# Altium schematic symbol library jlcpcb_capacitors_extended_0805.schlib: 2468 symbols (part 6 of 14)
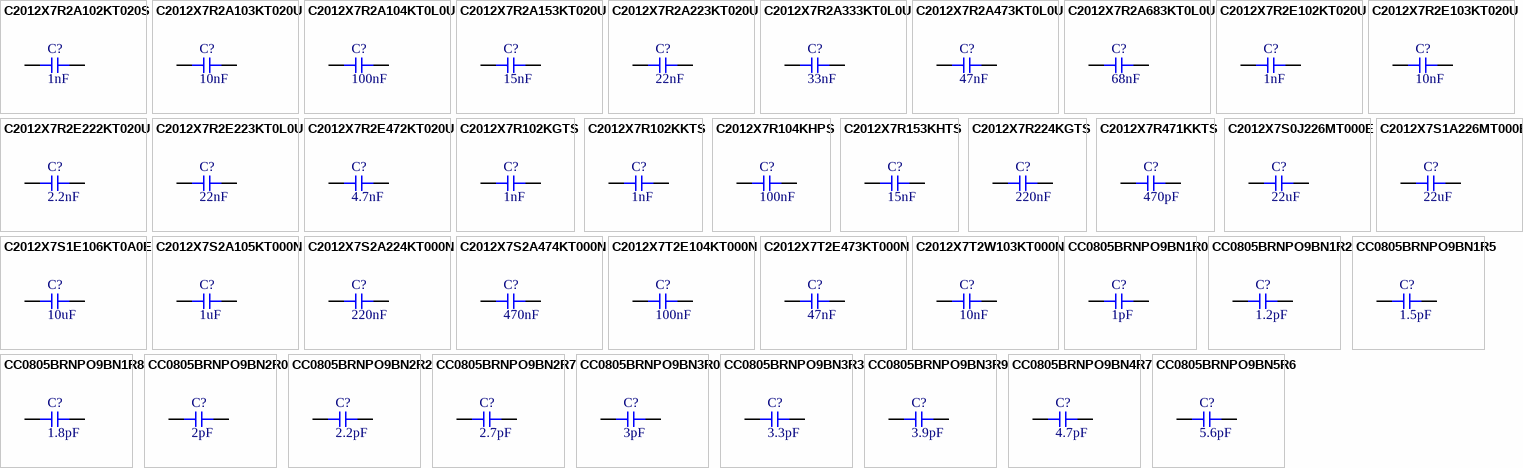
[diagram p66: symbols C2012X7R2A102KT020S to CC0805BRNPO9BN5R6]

## C2012X7T2E473KT000N
designator C?  Capacitance: 47nF  (hidden comment: *)
Capacitor, Ceramic (MLCC), 47nF, ±10%, 250V, X7T, ±10%, SMD 0805; Manufacturer: TDK; Manufacturer Part Number: C2012X7T2E473KT000N
footprint CAP-0805 (0805 (2012M) Capacitor)
pins: 1, 2

## C2012X7T2W103KT000N
designator C?  Capacitance: 10nF  (hidden comment: *)
Capacitor, Ceramic (MLCC), 10nF, ±10%, 450V, X7T, ±10%, SMD 0805; Manufacturer: TDK; Manufacturer Part Number: C2012X7T2W103KT000N
footprint CAP-0805 (0805 (2012M) Capacitor)
pins: 1, 2

## CC0805BRNPO9BN1R0
designator C?  Capacitance: 1pF  (hidden comment: *)
Capacitor, Ceramic (MLCC), 1pF, ±0.1pF, 50V, NP0, ±0.1pF, SMD 0805; Manufacturer: YAGEO; Manufacturer Part Number: CC0805BRNPO9BN1R0
footprint CAP-0805 (0805 (2012M) Capacitor)
pins: 1, 2

## CC0805BRNPO9BN1R2
designator C?  Capacitance: 1.2pF  (hidden comment: *)
Capacitor, Ceramic (MLCC), 1.2pF, ±0.1pF, 50V, NP0, ±0.1pF, SMD 0805; Manufacturer: YAGEO; Manufacturer Part Number: CC0805BRNPO9BN1R2
footprint CAP-0805 (0805 (2012M) Capacitor)
pins: 1, 2

## CC0805BRNPO9BN1R5
designator C?  Capacitance: 1.5pF  (hidden comment: *)
Capacitor, Ceramic (MLCC), 1.5pF, ±0.1pF, 50V, NP0, ±0.1pF, SMD 0805; Manufacturer: YAGEO; Manufacturer Part Number: CC0805BRNPO9BN1R5
footprint CAP-0805 (0805 (2012M) Capacitor)
pins: 1, 2

## CC0805BRNPO9BN1R8
designator C?  Capacitance: 1.8pF  (hidden comment: *)
Capacitor, Ceramic (MLCC), 1.8pF, ±0.1pF, 50V, NP0, ±0.1pF, SMD 0805; Manufacturer: YAGEO; Manufacturer Part Number: CC0805BRNPO9BN1R8
footprint CAP-0805 (0805 (2012M) Capacitor)
pins: 1, 2

## CC0805BRNPO9BN2R0
designator C?  Capacitance: 2pF  (hidden comment: *)
Capacitor, Ceramic (MLCC), 2pF, ±0.1pF, 50V, NP0, ±0.1pF, SMD 0805; Manufacturer: YAGEO; Manufacturer Part Number: CC0805BRNPO9BN2R0
footprint CAP-0805 (0805 (2012M) Capacitor)
pins: 1, 2

## CC0805BRNPO9BN2R2
designator C?  Capacitance: 2.2pF  (hidden comment: *)
Capacitor, Ceramic (MLCC), 2.2pF, ±0.1pF, 50V, NP0, ±0.1pF, SMD 0805; Manufacturer: YAGEO; Manufacturer Part Number: CC0805BRNPO9BN2R2
footprint CAP-0805 (0805 (2012M) Capacitor)
pins: 1, 2

## CC0805BRNPO9BN2R7
designator C?  Capacitance: 2.7pF  (hidden comment: *)
Capacitor, Ceramic (MLCC), 2.7pF, ±0.1pF, 50V, NP0, ±0.1pF, SMD 0805; Manufacturer: YAGEO; Manufacturer Part Number: CC0805BRNPO9BN2R7
footprint CAP-0805 (0805 (2012M) Capacitor)
pins: 1, 2

## CC0805BRNPO9BN3R0
designator C?  Capacitance: 3pF  (hidden comment: *)
Capacitor, Ceramic (MLCC), 3pF, ±0.1pF, 50V, NP0, ±0.1pF, SMD 0805; Manufacturer: YAGEO; Manufacturer Part Number: CC0805BRNPO9BN3R0
footprint CAP-0805 (0805 (2012M) Capacitor)
pins: 1, 2

## CC0805BRNPO9BN3R3
designator C?  Capacitance: 3.3pF  (hidden comment: *)
Capacitor, Ceramic (MLCC), 3.3pF, ±0.1pF, 50V, NP0, ±0.1pF, SMD 0805; Manufacturer: YAGEO; Manufacturer Part Number: CC0805BRNPO9BN3R3
footprint CAP-0805 (0805 (2012M) Capacitor)
pins: 1, 2

## CC0805BRNPO9BN3R9
designator C?  Capacitance: 3.9pF  (hidden comment: *)
Capacitor, Ceramic (MLCC), 3.9pF, ±0.1pF, 50V, NP0, ±0.1pF, SMD 0805; Manufacturer: YAGEO; Manufacturer Part Number: CC0805BRNPO9BN3R9
footprint CAP-0805 (0805 (2012M) Capacitor)
pins: 1, 2

## CC0805BRNPO9BN4R7
designator C?  Capacitance: 4.7pF  (hidden comment: *)
Capacitor, Ceramic (MLCC), 4.7pF, ±0.1pF, 50V, NP0, ±0.1pF, SMD 0805; Manufacturer: YAGEO; Manufacturer Part Number: CC0805BRNPO9BN4R7
footprint CAP-0805 (0805 (2012M) Capacitor)
pins: 1, 2

## CC0805BRNPO9BN5R6
designator C?  Capacitance: 5.6pF  (hidden comment: *)
Capacitor, Ceramic (MLCC), 5.6pF, ±0.1pF, 50V, NP0, ±0.1pF, SMD 0805; Manufacturer: YAGEO; Manufacturer Part Number: CC0805BRNPO9BN5R6
footprint CAP-0805 (0805 (2012M) Capacitor)
pins: 1, 2

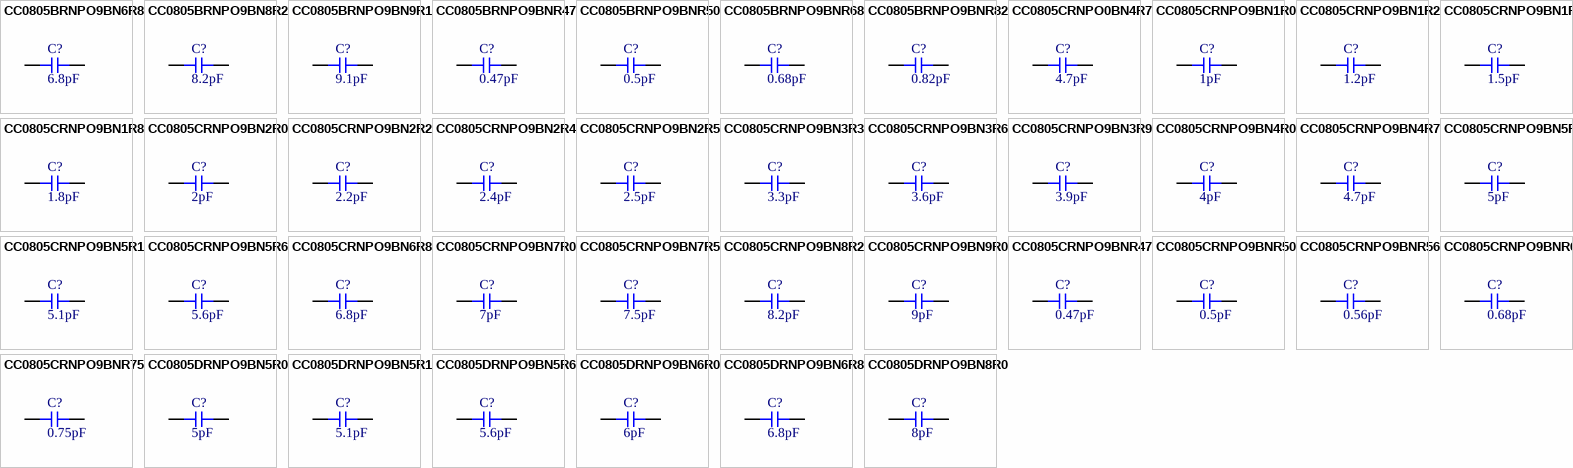
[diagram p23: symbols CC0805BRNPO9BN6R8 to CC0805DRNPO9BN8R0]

## CC0805BRNPO9BN6R8
designator C?  Capacitance: 6.8pF  (hidden comment: *)
Capacitor, Ceramic (MLCC), 6.8pF, ±0.1pF, 50V, NP0, ±0.1pF, SMD 0805; Manufacturer: YAGEO; Manufacturer Part Number: CC0805BRNPO9BN6R8
footprint CAP-0805 (0805 (2012M) Capacitor)
pins: 1, 2

## CC0805BRNPO9BN8R2
designator C?  Capacitance: 8.2pF  (hidden comment: *)
Capacitor, Ceramic (MLCC), 8.2pF, ±0.1pF, 50V, NP0, ±0.1pF, SMD 0805; Manufacturer: YAGEO; Manufacturer Part Number: CC0805BRNPO9BN8R2
footprint CAP-0805 (0805 (2012M) Capacitor)
pins: 1, 2

## CC0805BRNPO9BN9R1
designator C?  Capacitance: 9.1pF  (hidden comment: *)
Capacitor, Ceramic (MLCC), 9.1pF, ±0.1pF, 50V, NP0, ±0.1pF, SMD 0805; Manufacturer: YAGEO; Manufacturer Part Number: CC0805BRNPO9BN9R1
footprint CAP-0805 (0805 (2012M) Capacitor)
pins: 1, 2

## CC0805BRNPO9BNR47
designator C?  Capacitance: 0.47pF  (hidden comment: *)
Capacitor, Ceramic (MLCC), 0.47pF, ±0.1pF, 50V, NP0, ±0.1pF, SMD 0805; Manufacturer: YAGEO; Manufacturer Part Number: CC0805BRNPO9BNR47
footprint CAP-0805 (0805 (2012M) Capacitor)
pins: 1, 2

## CC0805BRNPO9BNR50
designator C?  Capacitance: 0.5pF  (hidden comment: *)
Capacitor, Ceramic (MLCC), 0.5pF, ±0.1pF, 50V, NP0, ±0.1pF, SMD 0805; Manufacturer: YAGEO; Manufacturer Part Number: CC0805BRNPO9BNR50
footprint CAP-0805 (0805 (2012M) Capacitor)
pins: 1, 2

## CC0805BRNPO9BNR68
designator C?  Capacitance: 0.68pF  (hidden comment: *)
Capacitor, Ceramic (MLCC), 0.68pF, ±0.1pF, 50V, NP0, ±0.1pF, SMD 0805; Manufacturer: YAGEO; Manufacturer Part Number: CC0805BRNPO9BNR68
footprint CAP-0805 (0805 (2012M) Capacitor)
pins: 1, 2

## CC0805BRNPO9BNR82
designator C?  Capacitance: 0.82pF  (hidden comment: *)
Capacitor, Ceramic (MLCC), 0.82pF, ±0.1pF, 50V, NP0, ±0.1pF, SMD 0805; Manufacturer: YAGEO; Manufacturer Part Number: CC0805BRNPO9BNR82
footprint CAP-0805 (0805 (2012M) Capacitor)
pins: 1, 2

## CC0805CRNPO0BN4R7
designator C?  Capacitance: 4.7pF  (hidden comment: *)
Capacitor, Ceramic (MLCC), 4.7pF, ±0.25pF, 100V, NP0, ±0.25pF, SMD 0805; Manufacturer: YAGEO; Manufacturer Part Number: CC0805CRNPO0BN4R7
footprint CAP-0805 (0805 (2012M) Capacitor)
pins: 1, 2

## CC0805CRNPO9BN1R0
designator C?  Capacitance: 1pF  (hidden comment: *)
Capacitor, Ceramic (MLCC), 1pF, ±0.25pF, 50V, NP0, ±0.25pF, SMD 0805; Manufacturer: YAGEO; Manufacturer Part Number: CC0805CRNPO9BN1R0
footprint CAP-0805 (0805 (2012M) Capacitor)
pins: 1, 2

## CC0805CRNPO9BN1R2
designator C?  Capacitance: 1.2pF  (hidden comment: *)
Capacitor, Ceramic (MLCC), 1.2pF, ±0.25pF, 50V, NP0, ±0.25pF, SMD 0805; Manufacturer: YAGEO; Manufacturer Part Number: CC0805CRNPO9BN1R2
footprint CAP-0805 (0805 (2012M) Capacitor)
pins: 1, 2

## CC0805CRNPO9BN1R5
designator C?  Capacitance: 1.5pF  (hidden comment: *)
Capacitor, Ceramic (MLCC), 1.5pF, ±0.25pF, 50V, NP0, ±0.25pF, SMD 0805; Manufacturer: YAGEO; Manufacturer Part Number: CC0805CRNPO9BN1R5
footprint CAP-0805 (0805 (2012M) Capacitor)
pins: 1, 2

## CC0805CRNPO9BN1R8
designator C?  Capacitance: 1.8pF  (hidden comment: *)
Capacitor, Ceramic (MLCC), 1.8pF, ±0.25pF, 50V, NP0, ±0.25pF, SMD 0805; Manufacturer: YAGEO; Manufacturer Part Number: CC0805CRNPO9BN1R8
footprint CAP-0805 (0805 (2012M) Capacitor)
pins: 1, 2

## CC0805CRNPO9BN2R0
designator C?  Capacitance: 2pF  (hidden comment: *)
Capacitor, Ceramic (MLCC), 2pF, ±0.25pF, 50V, NP0, ±0.25pF, SMD 0805; Manufacturer: YAGEO; Manufacturer Part Number: CC0805CRNPO9BN2R0
footprint CAP-0805 (0805 (2012M) Capacitor)
pins: 1, 2

## CC0805CRNPO9BN2R2
designator C?  Capacitance: 2.2pF  (hidden comment: *)
Capacitor, Ceramic (MLCC), 2.2pF, ±0.25pF, 50V, NP0, ±0.25pF, SMD 0805; Manufacturer: YAGEO; Manufacturer Part Number: CC0805CRNPO9BN2R2
footprint CAP-0805 (0805 (2012M) Capacitor)
pins: 1, 2

## CC0805CRNPO9BN2R4
designator C?  Capacitance: 2.4pF  (hidden comment: *)
Capacitor, Ceramic (MLCC), 2.4pF, ±0.25pF, 50V, NP0, ±0.25pF, SMD 0805; Manufacturer: YAGEO; Manufacturer Part Number: CC0805CRNPO9BN2R4
footprint CAP-0805 (0805 (2012M) Capacitor)
pins: 1, 2

## CC0805CRNPO9BN2R5
designator C?  Capacitance: 2.5pF  (hidden comment: *)
Capacitor, Ceramic (MLCC), 2.5pF, ±0.25pF, 50V, NP0, ±0.25pF, SMD 0805; Manufacturer: YAGEO; Manufacturer Part Number: CC0805CRNPO9BN2R5
footprint CAP-0805 (0805 (2012M) Capacitor)
pins: 1, 2

## CC0805CRNPO9BN3R3
designator C?  Capacitance: 3.3pF  (hidden comment: *)
Capacitor, Ceramic (MLCC), 3.3pF, ±0.25pF, 50V, NP0, ±0.25pF, SMD 0805; Manufacturer: YAGEO; Manufacturer Part Number: CC0805CRNPO9BN3R3
footprint CAP-0805 (0805 (2012M) Capacitor)
pins: 1, 2

## CC0805CRNPO9BN3R6
designator C?  Capacitance: 3.6pF  (hidden comment: *)
Capacitor, Ceramic (MLCC), 3.6pF, ±0.25pF, 50V, NP0, ±0.25pF, SMD 0805; Manufacturer: YAGEO; Manufacturer Part Number: CC0805CRNPO9BN3R6
footprint CAP-0805 (0805 (2012M) Capacitor)
pins: 1, 2

## CC0805CRNPO9BN3R9
designator C?  Capacitance: 3.9pF  (hidden comment: *)
Capacitor, Ceramic (MLCC), 3.9pF, ±0.25pF, 50V, NP0, ±0.25pF, SMD 0805; Manufacturer: YAGEO; Manufacturer Part Number: CC0805CRNPO9BN3R9
footprint CAP-0805 (0805 (2012M) Capacitor)
pins: 1, 2

## CC0805CRNPO9BN4R0
designator C?  Capacitance: 4pF  (hidden comment: *)
Capacitor, Ceramic (MLCC), 4pF, ±0.25pF, 50V, NP0, ±0.25pF, SMD 0805; Manufacturer: YAGEO; Manufacturer Part Number: CC0805CRNPO9BN4R0
footprint CAP-0805 (0805 (2012M) Capacitor)
pins: 1, 2

## CC0805CRNPO9BN4R7
designator C?  Capacitance: 4.7pF  (hidden comment: *)
Capacitor, Ceramic (MLCC), 4.7pF, ±0.25pF, 50V, NP0, ±0.25pF, SMD 0805; Manufacturer: YAGEO; Manufacturer Part Number: CC0805CRNPO9BN4R7
footprint CAP-0805 (0805 (2012M) Capacitor)
pins: 1, 2

## CC0805CRNPO9BN5R0
designator C?  Capacitance: 5pF  (hidden comment: *)
Capacitor, Ceramic (MLCC), 5pF, ±0.25pF, 50V, NP0, ±0.25pF, SMD 0805; Manufacturer: YAGEO; Manufacturer Part Number: CC0805CRNPO9BN5R0
footprint CAP-0805 (0805 (2012M) Capacitor)
pins: 1, 2

## CC0805CRNPO9BN5R1
designator C?  Capacitance: 5.1pF  (hidden comment: *)
Capacitor, Ceramic (MLCC), 5.1pF, ±0.25pF, 50V, NP0, ±0.25pF, SMD 0805; Manufacturer: YAGEO; Manufacturer Part Number: CC0805CRNPO9BN5R1
footprint CAP-0805 (0805 (2012M) Capacitor)
pins: 1, 2

## CC0805CRNPO9BN5R6
designator C?  Capacitance: 5.6pF  (hidden comment: *)
Capacitor, Ceramic (MLCC), 5.6pF, ±0.25pF, 50V, NP0, ±0.25pF, SMD 0805; Manufacturer: YAGEO; Manufacturer Part Number: CC0805CRNPO9BN5R6
footprint CAP-0805 (0805 (2012M) Capacitor)
pins: 1, 2

## CC0805CRNPO9BN6R8
designator C?  Capacitance: 6.8pF  (hidden comment: *)
Capacitor, Ceramic (MLCC), 6.8pF, ±0.25pF, 50V, NP0, ±0.25pF, SMD 0805; Manufacturer: YAGEO; Manufacturer Part Number: CC0805CRNPO9BN6R8
footprint CAP-0805 (0805 (2012M) Capacitor)
pins: 1, 2

## CC0805CRNPO9BN7R0
designator C?  Capacitance: 7pF  (hidden comment: *)
Capacitor, Ceramic (MLCC), 7pF, ±0.25pF, 50V, NP0, ±0.25pF, SMD 0805; Manufacturer: YAGEO; Manufacturer Part Number: CC0805CRNPO9BN7R0
footprint CAP-0805 (0805 (2012M) Capacitor)
pins: 1, 2

## CC0805CRNPO9BN7R5
designator C?  Capacitance: 7.5pF  (hidden comment: *)
Capacitor, Ceramic (MLCC), 7.5pF, ±0.25pF, 50V, NP0, ±0.25pF, SMD 0805; Manufacturer: YAGEO; Manufacturer Part Number: CC0805CRNPO9BN7R5
footprint CAP-0805 (0805 (2012M) Capacitor)
pins: 1, 2

## CC0805CRNPO9BN8R2
designator C?  Capacitance: 8.2pF  (hidden comment: *)
Capacitor, Ceramic (MLCC), 8.2pF, ±0.25pF, 50V, NP0, ±0.25pF, SMD 0805; Manufacturer: YAGEO; Manufacturer Part Number: CC0805CRNPO9BN8R2
footprint CAP-0805 (0805 (2012M) Capacitor)
pins: 1, 2

## CC0805CRNPO9BN9R0
designator C?  Capacitance: 9pF  (hidden comment: *)
Capacitor, Ceramic (MLCC), 9pF, ±0.25pF, 50V, NP0, ±0.25pF, SMD 0805; Manufacturer: YAGEO; Manufacturer Part Number: CC0805CRNPO9BN9R0
footprint CAP-0805 (0805 (2012M) Capacitor)
pins: 1, 2

## CC0805CRNPO9BNR47
designator C?  Capacitance: 0.47pF  (hidden comment: *)
Capacitor, Ceramic (MLCC), 0.47pF, ±0.25pF, 50V, NP0, ±0.25pF, SMD 0805; Manufacturer: YAGEO; Manufacturer Part Number: CC0805CRNPO9BNR47
footprint CAP-0805 (0805 (2012M) Capacitor)
pins: 1, 2

## CC0805CRNPO9BNR50
designator C?  Capacitance: 0.5pF  (hidden comment: *)
Capacitor, Ceramic (MLCC), 0.5pF, ±0.25pF, 50V, NP0, ±0.25pF, SMD 0805; Manufacturer: YAGEO; Manufacturer Part Number: CC0805CRNPO9BNR50
footprint CAP-0805 (0805 (2012M) Capacitor)
pins: 1, 2

## CC0805CRNPO9BNR56
designator C?  Capacitance: 0.56pF  (hidden comment: *)
Capacitor, Ceramic (MLCC), 0.56pF, ±0.25pF, 50V, NP0, ±0.25pF, SMD 0805; Manufacturer: YAGEO; Manufacturer Part Number: CC0805CRNPO9BNR56
footprint CAP-0805 (0805 (2012M) Capacitor)
pins: 1, 2

## CC0805CRNPO9BNR68
designator C?  Capacitance: 0.68pF  (hidden comment: *)
Capacitor, Ceramic (MLCC), 0.68pF, ±0.25pF, 50V, NP0, ±0.25pF, SMD 0805; Manufacturer: YAGEO; Manufacturer Part Number: CC0805CRNPO9BNR68
footprint CAP-0805 (0805 (2012M) Capacitor)
pins: 1, 2

## CC0805CRNPO9BNR75
designator C?  Capacitance: 0.75pF  (hidden comment: *)
Capacitor, Ceramic (MLCC), 0.75pF, ±0.25pF, 50V, NP0, ±0.25pF, SMD 0805; Manufacturer: YAGEO; Manufacturer Part Number: CC0805CRNPO9BNR75
footprint CAP-0805 (0805 (2012M) Capacitor)
pins: 1, 2

## CC0805DRNPO9BN5R0
designator C?  Capacitance: 5pF  (hidden comment: *)
Capacitor, Ceramic (MLCC), 5pF, ±0.5pF, 50V, NP0, ±0.5pF, SMD 0805; Manufacturer: YAGEO; Manufacturer Part Number: CC0805DRNPO9BN5R0
footprint CAP-0805 (0805 (2012M) Capacitor)
pins: 1, 2

## CC0805DRNPO9BN5R1
designator C?  Capacitance: 5.1pF  (hidden comment: *)
Capacitor, Ceramic (MLCC), 5.1pF, ±0.5pF, 50V, NP0, ±0.5pF, SMD 0805; Manufacturer: YAGEO; Manufacturer Part Number: CC0805DRNPO9BN5R1
footprint CAP-0805 (0805 (2012M) Capacitor)
pins: 1, 2

## CC0805DRNPO9BN5R6
designator C?  Capacitance: 5.6pF  (hidden comment: *)
Capacitor, Ceramic (MLCC), 5.6pF, ±0.5pF, 50V, NP0, ±0.5pF, SMD 0805; Manufacturer: YAGEO; Manufacturer Part Number: CC0805DRNPO9BN5R6
footprint CAP-0805 (0805 (2012M) Capacitor)
pins: 1, 2

## CC0805DRNPO9BN6R0
designator C?  Capacitance: 6pF  (hidden comment: *)
Capacitor, Ceramic (MLCC), 6pF, ±0.5pF, 50V, NP0, ±0.5pF, SMD 0805; Manufacturer: YAGEO; Manufacturer Part Number: CC0805DRNPO9BN6R0
footprint CAP-0805 (0805 (2012M) Capacitor)
pins: 1, 2

## CC0805DRNPO9BN6R8
designator C?  Capacitance: 6.8pF  (hidden comment: *)
Capacitor, Ceramic (MLCC), 6.8pF, ±0.5pF, 50V, NP0, ±0.5pF, SMD 0805; Manufacturer: YAGEO; Manufacturer Part Number: CC0805DRNPO9BN6R8
footprint CAP-0805 (0805 (2012M) Capacitor)
pins: 1, 2

## CC0805DRNPO9BN8R0
designator C?  Capacitance: 8pF  (hidden comment: *)
Capacitor, Ceramic (MLCC), 8pF, ±0.5pF, 50V, NP0, ±0.5pF, SMD 0805; Manufacturer: YAGEO; Manufacturer Part Number: CC0805DRNPO9BN8R0
footprint CAP-0805 (0805 (2012M) Capacitor)
pins: 1, 2

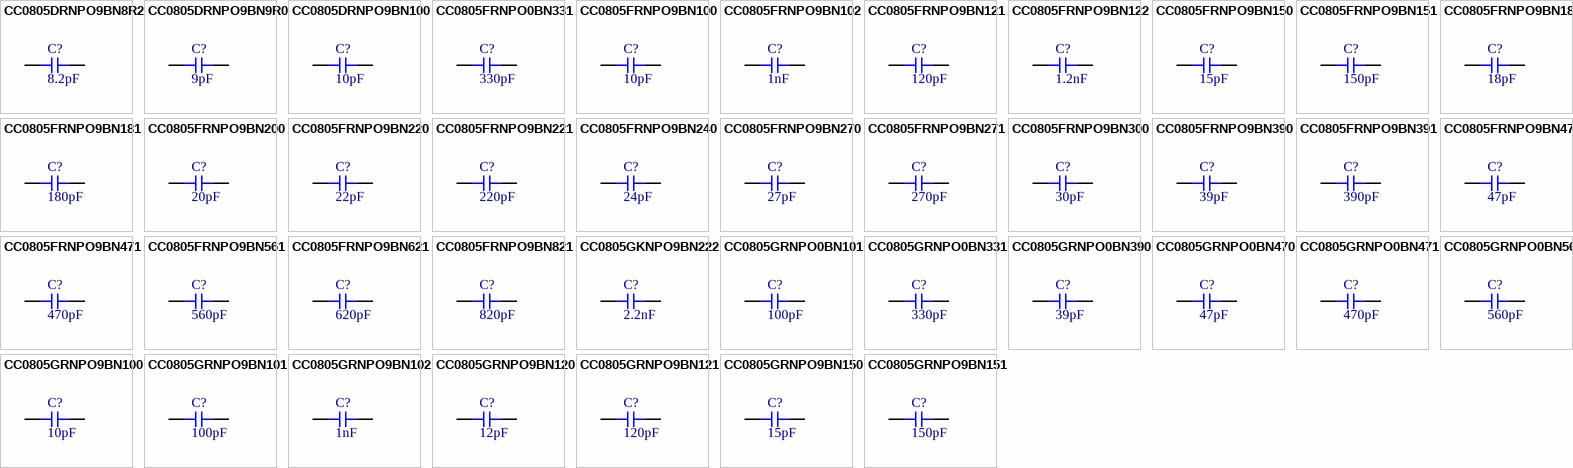
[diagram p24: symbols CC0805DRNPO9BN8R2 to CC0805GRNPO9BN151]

## CC0805DRNPO9BN8R2
designator C?  Capacitance: 8.2pF  (hidden comment: *)
Capacitor, Ceramic (MLCC), 8.2pF, ±0.5pF, 50V, NP0, ±0.5pF, SMD 0805; Manufacturer: YAGEO; Manufacturer Part Number: CC0805DRNPO9BN8R2
footprint CAP-0805 (0805 (2012M) Capacitor)
pins: 1, 2

## CC0805DRNPO9BN9R0
designator C?  Capacitance: 9pF  (hidden comment: *)
Capacitor, Ceramic (MLCC), 9pF, ±0.5pF, 50V, NP0, ±0.5pF, SMD 0805; Manufacturer: YAGEO; Manufacturer Part Number: CC0805DRNPO9BN9R0
footprint CAP-0805 (0805 (2012M) Capacitor)
pins: 1, 2

## CC0805DRNPO9BN100
designator C?  Capacitance: 10pF  (hidden comment: *)
Capacitor, Ceramic (MLCC), 10pF, ±0.5pF, 50V, NP0, ±0.5pF, SMD 0805; Manufacturer: YAGEO; Manufacturer Part Number: CC0805DRNPO9BN100
footprint CAP-0805 (0805 (2012M) Capacitor)
pins: 1, 2

## CC0805FRNPO0BN331
designator C?  Capacitance: 330pF  (hidden comment: *)
Capacitor, Ceramic (MLCC), 330pF, ±1%, 100V, NP0, ±1%, SMD 0805; Manufacturer: YAGEO; Manufacturer Part Number: CC0805FRNPO0BN331
footprint CAP-0805 (0805 (2012M) Capacitor)
pins: 1, 2

## CC0805FRNPO9BN100
designator C?  Capacitance: 10pF  (hidden comment: *)
Capacitor, Ceramic (MLCC), 10pF, ±1pF, 50V, NP0, ±1pF, SMD 0805; Manufacturer: YAGEO; Manufacturer Part Number: CC0805FRNPO9BN100
footprint CAP-0805 (0805 (2012M) Capacitor)
pins: 1, 2

## CC0805FRNPO9BN102
designator C?  Capacitance: 1nF  (hidden comment: *)
Capacitor, Ceramic (MLCC), 1nF, ±1%, 50V, NP0, ±1%, SMD 0805; Manufacturer: YAGEO; Manufacturer Part Number: CC0805FRNPO9BN102
footprint CAP-0805 (0805 (2012M) Capacitor)
pins: 1, 2

## CC0805FRNPO9BN121
designator C?  Capacitance: 120pF  (hidden comment: *)
Capacitor, Ceramic (MLCC), 120pF, ±1%, 50V, NP0, ±1%, SMD 0805; Manufacturer: YAGEO; Manufacturer Part Number: CC0805FRNPO9BN121
footprint CAP-0805 (0805 (2012M) Capacitor)
pins: 1, 2

## CC0805FRNPO9BN122
designator C?  Capacitance: 1.2nF  (hidden comment: *)
Capacitor, Ceramic (MLCC), 1.2nF, ±1pF, 50V, NP0, ±1pF, SMD 0805; Manufacturer: YAGEO; Manufacturer Part Number: CC0805FRNPO9BN122
footprint CAP-0805 (0805 (2012M) Capacitor)
pins: 1, 2

## CC0805FRNPO9BN150
designator C?  Capacitance: 15pF  (hidden comment: *)
Capacitor, Ceramic (MLCC), 15pF, ±1%, 50V, NP0, ±1%, SMD 0805; Manufacturer: YAGEO; Manufacturer Part Number: CC0805FRNPO9BN150
footprint CAP-0805 (0805 (2012M) Capacitor)
pins: 1, 2

## CC0805FRNPO9BN151
designator C?  Capacitance: 150pF  (hidden comment: *)
Capacitor, Ceramic (MLCC), 150pF, ±1%, 50V, NP0, ±1%, SMD 0805; Manufacturer: YAGEO; Manufacturer Part Number: CC0805FRNPO9BN151
footprint CAP-0805 (0805 (2012M) Capacitor)
pins: 1, 2

## CC0805FRNPO9BN180
designator C?  Capacitance: 18pF  (hidden comment: *)
Capacitor, Ceramic (MLCC), 18pF, ±1%, 50V, NP0, ±1%, SMD 0805; Manufacturer: YAGEO; Manufacturer Part Number: CC0805FRNPO9BN180
footprint CAP-0805 (0805 (2012M) Capacitor)
pins: 1, 2

## CC0805FRNPO9BN181
designator C?  Capacitance: 180pF  (hidden comment: *)
Capacitor, Ceramic (MLCC), 180pF, ±1%, 50V, NP0, ±1%, SMD 0805; Manufacturer: YAGEO; Manufacturer Part Number: CC0805FRNPO9BN181
footprint CAP-0805 (0805 (2012M) Capacitor)
pins: 1, 2

## CC0805FRNPO9BN200
designator C?  Capacitance: 20pF  (hidden comment: *)
Capacitor, Ceramic (MLCC), 20pF, ±1%, 50V, NP0, ±1%, SMD 0805; Manufacturer: YAGEO; Manufacturer Part Number: CC0805FRNPO9BN200
footprint CAP-0805 (0805 (2012M) Capacitor)
pins: 1, 2

## CC0805FRNPO9BN220
designator C?  Capacitance: 22pF  (hidden comment: *)
Capacitor, Ceramic (MLCC), 22pF, ±1pF, 50V, NP0, ±1pF, SMD 0805; Manufacturer: YAGEO; Manufacturer Part Number: CC0805FRNPO9BN220
footprint CAP-0805 (0805 (2012M) Capacitor)
pins: 1, 2

## CC0805FRNPO9BN221
designator C?  Capacitance: 220pF  (hidden comment: *)
Capacitor, Ceramic (MLCC), 220pF, ±1pF, 50V, NP0, ±1pF, SMD 0805; Manufacturer: YAGEO; Manufacturer Part Number: CC0805FRNPO9BN221
footprint CAP-0805 (0805 (2012M) Capacitor)
pins: 1, 2

## CC0805FRNPO9BN240
designator C?  Capacitance: 24pF  (hidden comment: *)
Capacitor, Ceramic (MLCC), 24pF, ±1%, 50V, NP0, ±1%, SMD 0805; Manufacturer: YAGEO; Manufacturer Part Number: CC0805FRNPO9BN240
footprint CAP-0805 (0805 (2012M) Capacitor)
pins: 1, 2

## CC0805FRNPO9BN270
designator C?  Capacitance: 27pF  (hidden comment: *)
Capacitor, Ceramic (MLCC), 27pF, ±1%, 50V, NP0, ±1%, SMD 0805; Manufacturer: YAGEO; Manufacturer Part Number: CC0805FRNPO9BN270
footprint CAP-0805 (0805 (2012M) Capacitor)
pins: 1, 2

## CC0805FRNPO9BN271
designator C?  Capacitance: 270pF  (hidden comment: *)
Capacitor, Ceramic (MLCC), 270pF, ±1%, 50V, NP0, ±1%, SMD 0805; Manufacturer: YAGEO; Manufacturer Part Number: CC0805FRNPO9BN271
footprint CAP-0805 (0805 (2012M) Capacitor)
pins: 1, 2

## CC0805FRNPO9BN300
designator C?  Capacitance: 30pF  (hidden comment: *)
Capacitor, Ceramic (MLCC), 30pF, ±1%, 50V, NP0, ±1%, SMD 0805; Manufacturer: YAGEO; Manufacturer Part Number: CC0805FRNPO9BN300
footprint CAP-0805 (0805 (2012M) Capacitor)
pins: 1, 2

## CC0805FRNPO9BN390
designator C?  Capacitance: 39pF  (hidden comment: *)
Capacitor, Ceramic (MLCC), 39pF, ±1%, 50V, NP0, ±1%, SMD 0805; Manufacturer: YAGEO; Manufacturer Part Number: CC0805FRNPO9BN390
footprint CAP-0805 (0805 (2012M) Capacitor)
pins: 1, 2

## CC0805FRNPO9BN391
designator C?  Capacitance: 390pF  (hidden comment: *)
Capacitor, Ceramic (MLCC), 390pF, ±1%, 50V, NP0, ±1%, SMD 0805; Manufacturer: YAGEO; Manufacturer Part Number: CC0805FRNPO9BN391
footprint CAP-0805 (0805 (2012M) Capacitor)
pins: 1, 2

## CC0805FRNPO9BN470
designator C?  Capacitance: 47pF  (hidden comment: *)
Capacitor, Ceramic (MLCC), 47pF, ±1%, 50V, NP0, ±1%, SMD 0805; Manufacturer: YAGEO; Manufacturer Part Number: CC0805FRNPO9BN470
footprint CAP-0805 (0805 (2012M) Capacitor)
pins: 1, 2

## CC0805FRNPO9BN471
designator C?  Capacitance: 470pF  (hidden comment: *)
Capacitor, Ceramic (MLCC), 470pF, ±1%, 50V, NP0, ±1%, SMD 0805; Manufacturer: YAGEO; Manufacturer Part Number: CC0805FRNPO9BN471
footprint CAP-0805 (0805 (2012M) Capacitor)
pins: 1, 2

## CC0805FRNPO9BN561
designator C?  Capacitance: 560pF  (hidden comment: *)
Capacitor, Ceramic (MLCC), 560pF, ±1%, 50V, NP0, ±1%, SMD 0805; Manufacturer: YAGEO; Manufacturer Part Number: CC0805FRNPO9BN561
footprint CAP-0805 (0805 (2012M) Capacitor)
pins: 1, 2

## CC0805FRNPO9BN621
designator C?  Capacitance: 620pF  (hidden comment: *)
Capacitor, Ceramic (MLCC), 620pF, ±1pF, 50V, NP0, ±1pF, SMD 0805; Manufacturer: YAGEO; Manufacturer Part Number: CC0805FRNPO9BN621
footprint CAP-0805 (0805 (2012M) Capacitor)
pins: 1, 2

## CC0805FRNPO9BN821
designator C?  Capacitance: 820pF  (hidden comment: *)
Capacitor, Ceramic (MLCC), 820pF, ±1%, 50V, NP0, ±1%, SMD 0805; Manufacturer: YAGEO; Manufacturer Part Number: CC0805FRNPO9BN821
footprint CAP-0805 (0805 (2012M) Capacitor)
pins: 1, 2

## CC0805GKNPO9BN222
designator C?  Capacitance: 2.2nF  (hidden comment: *)
Capacitor, Ceramic (MLCC), 2.2nF, ±2%, 50V, NP0, ±2%, SMD 0805; Manufacturer: YAGEO; Manufacturer Part Number: CC0805GKNPO9BN222
footprint CAP-0805 (0805 (2012M) Capacitor)
pins: 1, 2

## CC0805GRNPO0BN101
designator C?  Capacitance: 100pF  (hidden comment: *)
Capacitor, Ceramic (MLCC), 100pF, ±2%, 100V, NP0, ±2%, SMD 0805; Manufacturer: YAGEO; Manufacturer Part Number: CC0805GRNPO0BN101
footprint CAP-0805 (0805 (2012M) Capacitor)
pins: 1, 2

## CC0805GRNPO0BN331
designator C?  Capacitance: 330pF  (hidden comment: *)
Capacitor, Ceramic (MLCC), 330pF, ±2%, 100V, NP0, ±2%, SMD 0805; Manufacturer: YAGEO; Manufacturer Part Number: CC0805GRNPO0BN331
footprint CAP-0805 (0805 (2012M) Capacitor)
pins: 1, 2

## CC0805GRNPO0BN390
designator C?  Capacitance: 39pF  (hidden comment: *)
Capacitor, Ceramic (MLCC), 39pF, ±2%, 100V, NP0, ±2%, SMD 0805; Manufacturer: YAGEO; Manufacturer Part Number: CC0805GRNPO0BN390
footprint CAP-0805 (0805 (2012M) Capacitor)
pins: 1, 2

## CC0805GRNPO0BN470
designator C?  Capacitance: 47pF  (hidden comment: *)
Capacitor, Ceramic (MLCC), 47pF, ±2%, 100V, NP0, ±2%, SMD 0805; Manufacturer: YAGEO; Manufacturer Part Number: CC0805GRNPO0BN470
footprint CAP-0805 (0805 (2012M) Capacitor)
pins: 1, 2

## CC0805GRNPO0BN471
designator C?  Capacitance: 470pF  (hidden comment: *)
Capacitor, Ceramic (MLCC), 470pF, ±2%, 100V, NP0, ±2%, SMD 0805; Manufacturer: YAGEO; Manufacturer Part Number: CC0805GRNPO0BN471
footprint CAP-0805 (0805 (2012M) Capacitor)
pins: 1, 2

## CC0805GRNPO0BN561
designator C?  Capacitance: 560pF  (hidden comment: *)
Capacitor, Ceramic (MLCC), 560pF, ±2%, 100V, NP0, ±2%, SMD 0805; Manufacturer: YAGEO; Manufacturer Part Number: CC0805GRNPO0BN561
footprint CAP-0805 (0805 (2012M) Capacitor)
pins: 1, 2

## CC0805GRNPO9BN100
designator C?  Capacitance: 10pF  (hidden comment: *)
Capacitor, Ceramic (MLCC), 10pF, ±2%, 50V, NP0, ±2%, SMD 0805; Manufacturer: YAGEO; Manufacturer Part Number: CC0805GRNPO9BN100
footprint CAP-0805 (0805 (2012M) Capacitor)
pins: 1, 2

## CC0805GRNPO9BN101
designator C?  Capacitance: 100pF  (hidden comment: *)
Capacitor, Ceramic (MLCC), 100pF, ±2%, 50V, NP0, ±2%, SMD 0805; Manufacturer: YAGEO; Manufacturer Part Number: CC0805GRNPO9BN101
footprint CAP-0805 (0805 (2012M) Capacitor)
pins: 1, 2

## CC0805GRNPO9BN102
designator C?  Capacitance: 1nF  (hidden comment: *)
Capacitor, Ceramic (MLCC), 1nF, ±2%, 50V, NP0, ±2%, SMD 0805; Manufacturer: YAGEO; Manufacturer Part Number: CC0805GRNPO9BN102
footprint CAP-0805 (0805 (2012M) Capacitor)
pins: 1, 2

## CC0805GRNPO9BN120
designator C?  Capacitance: 12pF  (hidden comment: *)
Capacitor, Ceramic (MLCC), 12pF, ±2%, 50V, NP0, ±2%, SMD 0805; Manufacturer: YAGEO; Manufacturer Part Number: CC0805GRNPO9BN120
footprint CAP-0805 (0805 (2012M) Capacitor)
pins: 1, 2

## CC0805GRNPO9BN121
designator C?  Capacitance: 120pF  (hidden comment: *)
Capacitor, Ceramic (MLCC), 120pF, ±2%, 50V, NP0, ±2%, SMD 0805; Manufacturer: YAGEO; Manufacturer Part Number: CC0805GRNPO9BN121
footprint CAP-0805 (0805 (2012M) Capacitor)
pins: 1, 2

## CC0805GRNPO9BN150
designator C?  Capacitance: 15pF  (hidden comment: *)
Capacitor, Ceramic (MLCC), 15pF, ±2%, 50V, NP0, ±2%, SMD 0805; Manufacturer: YAGEO; Manufacturer Part Number: CC0805GRNPO9BN150
footprint CAP-0805 (0805 (2012M) Capacitor)
pins: 1, 2

## CC0805GRNPO9BN151
designator C?  Capacitance: 150pF  (hidden comment: *)
Capacitor, Ceramic (MLCC), 150pF, ±2%, 50V, NP0, ±2%, SMD 0805; Manufacturer: YAGEO; Manufacturer Part Number: CC0805GRNPO9BN151
footprint CAP-0805 (0805 (2012M) Capacitor)
pins: 1, 2

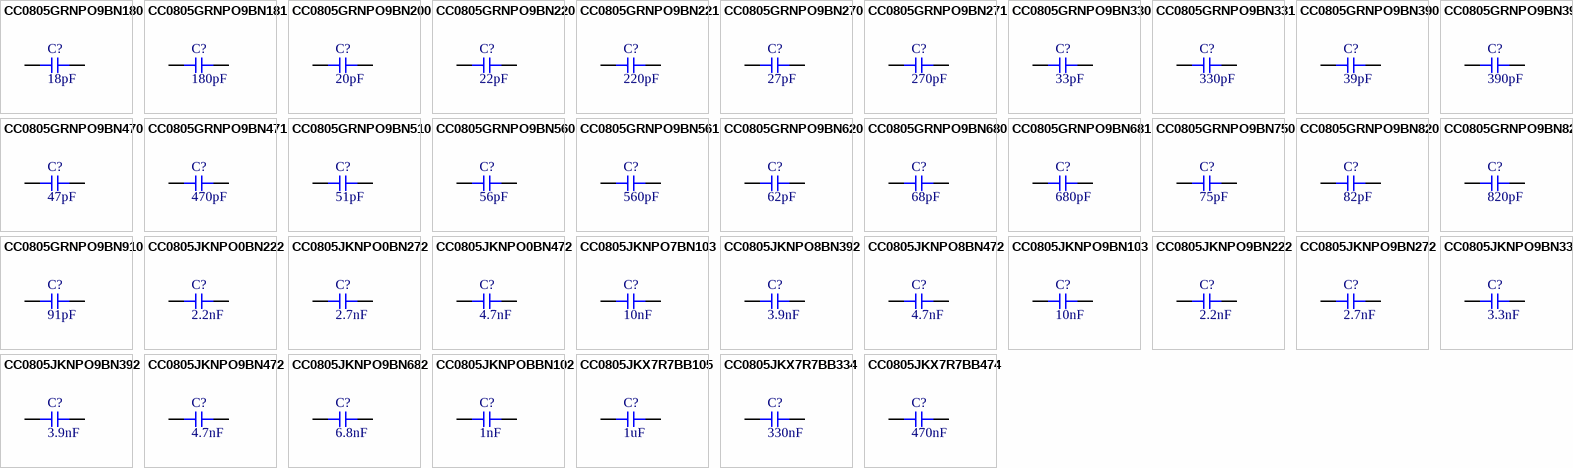
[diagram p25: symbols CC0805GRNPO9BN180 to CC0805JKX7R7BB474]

## CC0805GRNPO9BN180
designator C?  Capacitance: 18pF  (hidden comment: *)
Capacitor, Ceramic (MLCC), 18pF, ±2%, 50V, NP0, ±2%, SMD 0805; Manufacturer: YAGEO; Manufacturer Part Number: CC0805GRNPO9BN180
footprint CAP-0805 (0805 (2012M) Capacitor)
pins: 1, 2

## CC0805GRNPO9BN181
designator C?  Capacitance: 180pF  (hidden comment: *)
Capacitor, Ceramic (MLCC), 180pF, ±2%, 50V, NP0, ±2%, SMD 0805; Manufacturer: YAGEO; Manufacturer Part Number: CC0805GRNPO9BN181
footprint CAP-0805 (0805 (2012M) Capacitor)
pins: 1, 2

## CC0805GRNPO9BN200
designator C?  Capacitance: 20pF  (hidden comment: *)
Capacitor, Ceramic (MLCC), 20pF, ±2%, 50V, NP0, ±2%, SMD 0805; Manufacturer: YAGEO; Manufacturer Part Number: CC0805GRNPO9BN200
footprint CAP-0805 (0805 (2012M) Capacitor)
pins: 1, 2

## CC0805GRNPO9BN220
designator C?  Capacitance: 22pF  (hidden comment: *)
Capacitor, Ceramic (MLCC), 22pF, ±2%, 50V, NP0, ±2%, SMD 0805; Manufacturer: YAGEO; Manufacturer Part Number: CC0805GRNPO9BN220
footprint CAP-0805 (0805 (2012M) Capacitor)
pins: 1, 2

## CC0805GRNPO9BN221
designator C?  Capacitance: 220pF  (hidden comment: *)
Capacitor, Ceramic (MLCC), 220pF, ±2%, 50V, NP0, ±2%, SMD 0805; Manufacturer: YAGEO; Manufacturer Part Number: CC0805GRNPO9BN221
footprint CAP-0805 (0805 (2012M) Capacitor)
pins: 1, 2

## CC0805GRNPO9BN270
designator C?  Capacitance: 27pF  (hidden comment: *)
Capacitor, Ceramic (MLCC), 27pF, ±2%, 50V, NP0, ±2%, SMD 0805; Manufacturer: YAGEO; Manufacturer Part Number: CC0805GRNPO9BN270
footprint CAP-0805 (0805 (2012M) Capacitor)
pins: 1, 2

## CC0805GRNPO9BN271
designator C?  Capacitance: 270pF  (hidden comment: *)
Capacitor, Ceramic (MLCC), 270pF, ±2%, 50V, NP0, ±2%, SMD 0805; Manufacturer: YAGEO; Manufacturer Part Number: CC0805GRNPO9BN271
footprint CAP-0805 (0805 (2012M) Capacitor)
pins: 1, 2

## CC0805GRNPO9BN330
designator C?  Capacitance: 33pF  (hidden comment: *)
Capacitor, Ceramic (MLCC), 33pF, ±2%, 50V, NP0, ±2%, SMD 0805; Manufacturer: YAGEO; Manufacturer Part Number: CC0805GRNPO9BN330
footprint CAP-0805 (0805 (2012M) Capacitor)
pins: 1, 2

## CC0805GRNPO9BN331
designator C?  Capacitance: 330pF  (hidden comment: *)
Capacitor, Ceramic (MLCC), 330pF, ±2%, 50V, NP0, ±2%, SMD 0805; Manufacturer: YAGEO; Manufacturer Part Number: CC0805GRNPO9BN331
footprint CAP-0805 (0805 (2012M) Capacitor)
pins: 1, 2

## CC0805GRNPO9BN390
designator C?  Capacitance: 39pF  (hidden comment: *)
Capacitor, Ceramic (MLCC), 39pF, ±2%, 50V, NP0, ±2%, SMD 0805; Manufacturer: YAGEO; Manufacturer Part Number: CC0805GRNPO9BN390
footprint CAP-0805 (0805 (2012M) Capacitor)
pins: 1, 2

## CC0805GRNPO9BN391
designator C?  Capacitance: 390pF  (hidden comment: *)
Capacitor, Ceramic (MLCC), 390pF, ±2%, 50V, NP0, ±2%, SMD 0805; Manufacturer: YAGEO; Manufacturer Part Number: CC0805GRNPO9BN391
footprint CAP-0805 (0805 (2012M) Capacitor)
pins: 1, 2

## CC0805GRNPO9BN470
designator C?  Capacitance: 47pF  (hidden comment: *)
Capacitor, Ceramic (MLCC), 47pF, ±2%, 50V, NP0, ±2%, SMD 0805; Manufacturer: YAGEO; Manufacturer Part Number: CC0805GRNPO9BN470
footprint CAP-0805 (0805 (2012M) Capacitor)
pins: 1, 2

## CC0805GRNPO9BN471
designator C?  Capacitance: 470pF  (hidden comment: *)
Capacitor, Ceramic (MLCC), 470pF, ±2%, 50V, NP0, ±2%, SMD 0805; Manufacturer: YAGEO; Manufacturer Part Number: CC0805GRNPO9BN471
footprint CAP-0805 (0805 (2012M) Capacitor)
pins: 1, 2

## CC0805GRNPO9BN510
designator C?  Capacitance: 51pF  (hidden comment: *)
Capacitor, Ceramic (MLCC), 51pF, ±2%, 50V, NP0, ±2%, SMD 0805; Manufacturer: YAGEO; Manufacturer Part Number: CC0805GRNPO9BN510
footprint CAP-0805 (0805 (2012M) Capacitor)
pins: 1, 2

## CC0805GRNPO9BN560
designator C?  Capacitance: 56pF  (hidden comment: *)
Capacitor, Ceramic (MLCC), 56pF, ±2%, 50V, NP0, ±2%, SMD 0805; Manufacturer: YAGEO; Manufacturer Part Number: CC0805GRNPO9BN560
footprint CAP-0805 (0805 (2012M) Capacitor)
pins: 1, 2

## CC0805GRNPO9BN561
designator C?  Capacitance: 560pF  (hidden comment: *)
Capacitor, Ceramic (MLCC), 560pF, ±2%, 50V, NP0, ±2%, SMD 0805; Manufacturer: YAGEO; Manufacturer Part Number: CC0805GRNPO9BN561
footprint CAP-0805 (0805 (2012M) Capacitor)
pins: 1, 2

## CC0805GRNPO9BN620
designator C?  Capacitance: 62pF  (hidden comment: *)
Capacitor, Ceramic (MLCC), 62pF, ±2%, 50V, NP0, ±2%, SMD 0805; Manufacturer: YAGEO; Manufacturer Part Number: CC0805GRNPO9BN620
footprint CAP-0805 (0805 (2012M) Capacitor)
pins: 1, 2

## CC0805GRNPO9BN680
designator C?  Capacitance: 68pF  (hidden comment: *)
Capacitor, Ceramic (MLCC), 68pF, ±2%, 50V, NP0, ±2%, SMD 0805; Manufacturer: YAGEO; Manufacturer Part Number: CC0805GRNPO9BN680
footprint CAP-0805 (0805 (2012M) Capacitor)
pins: 1, 2

## CC0805GRNPO9BN681
designator C?  Capacitance: 680pF  (hidden comment: *)
Capacitor, Ceramic (MLCC), 680pF, ±2%, 50V, NP0, ±2%, SMD 0805; Manufacturer: YAGEO; Manufacturer Part Number: CC0805GRNPO9BN681
footprint CAP-0805 (0805 (2012M) Capacitor)
pins: 1, 2

## CC0805GRNPO9BN750
designator C?  Capacitance: 75pF  (hidden comment: *)
Capacitor, Ceramic (MLCC), 75pF, ±2%, 50V, NP0, ±2%, SMD 0805; Manufacturer: YAGEO; Manufacturer Part Number: CC0805GRNPO9BN750
footprint CAP-0805 (0805 (2012M) Capacitor)
pins: 1, 2

## CC0805GRNPO9BN820
designator C?  Capacitance: 82pF  (hidden comment: *)
Capacitor, Ceramic (MLCC), 82pF, ±2%, 50V, NP0, ±2%, SMD 0805; Manufacturer: YAGEO; Manufacturer Part Number: CC0805GRNPO9BN820
footprint CAP-0805 (0805 (2012M) Capacitor)
pins: 1, 2

## CC0805GRNPO9BN821
designator C?  Capacitance: 820pF  (hidden comment: *)
Capacitor, Ceramic (MLCC), 820pF, ±2%, 50V, NP0, ±2%, SMD 0805; Manufacturer: YAGEO; Manufacturer Part Number: CC0805GRNPO9BN821
footprint CAP-0805 (0805 (2012M) Capacitor)
pins: 1, 2

## CC0805GRNPO9BN910
designator C?  Capacitance: 91pF  (hidden comment: *)
Capacitor, Ceramic (MLCC), 91pF, ±2%, 50V, NP0, ±2%, SMD 0805; Manufacturer: YAGEO; Manufacturer Part Number: CC0805GRNPO9BN910
footprint CAP-0805 (0805 (2012M) Capacitor)
pins: 1, 2

## CC0805JKNPO0BN222
designator C?  Capacitance: 2.2nF  (hidden comment: *)
Capacitor, Ceramic (MLCC), 2.2nF, ±5%, 100V, NP0, ±5%, SMD 0805; Manufacturer: YAGEO; Manufacturer Part Number: CC0805JKNPO0BN222
footprint CAP-0805 (0805 (2012M) Capacitor)
pins: 1, 2

## CC0805JKNPO0BN272
designator C?  Capacitance: 2.7nF  (hidden comment: *)
Capacitor, Ceramic (MLCC), 2.7nF, ±5%, 100V, NP0, ±5%, SMD 0805; Manufacturer: YAGEO; Manufacturer Part Number: CC0805JKNPO0BN272
footprint CAP-0805 (0805 (2012M) Capacitor)
pins: 1, 2

## CC0805JKNPO0BN472
designator C?  Capacitance: 4.7nF  (hidden comment: *)
Capacitor, Ceramic (MLCC), 4.7nF, ±5%, 100V, NP0, ±5%, SMD 0805; Manufacturer: YAGEO; Manufacturer Part Number: CC0805JKNPO0BN472
footprint CAP-0805 (0805 (2012M) Capacitor)
pins: 1, 2

## CC0805JKNPO7BN103
designator C?  Capacitance: 10nF  (hidden comment: *)
Capacitor, Ceramic (MLCC), 10nF, ±5%, 16V, NP0, ±5%, SMD 0805; Manufacturer: YAGEO; Manufacturer Part Number: CC0805JKNPO7BN103
footprint CAP-0805 (0805 (2012M) Capacitor)
pins: 1, 2

## CC0805JKNPO8BN392
designator C?  Capacitance: 3.9nF  (hidden comment: *)
Capacitor, Ceramic (MLCC), 3.9nF, ±5%, 25V, NP0, ±5%, SMD 0805; Manufacturer: YAGEO; Manufacturer Part Number: CC0805JKNPO8BN392
footprint CAP-0805 (0805 (2012M) Capacitor)
pins: 1, 2

## CC0805JKNPO8BN472
designator C?  Capacitance: 4.7nF  (hidden comment: *)
Capacitor, Ceramic (MLCC), 4.7nF, ±5%, 25V, NP0, ±5%, SMD 0805; Manufacturer: YAGEO; Manufacturer Part Number: CC0805JKNPO8BN472
footprint CAP-0805 (0805 (2012M) Capacitor)
pins: 1, 2

## CC0805JKNPO9BN103
designator C?  Capacitance: 10nF  (hidden comment: *)
Capacitor, Ceramic (MLCC), 10nF, ±5%, 50V, NP0, ±5%, SMD 0805; Manufacturer: YAGEO; Manufacturer Part Number: CC0805JKNPO9BN103
footprint CAP-0805 (0805 (2012M) Capacitor)
pins: 1, 2

## CC0805JKNPO9BN222
designator C?  Capacitance: 2.2nF  (hidden comment: *)
Capacitor, Ceramic (MLCC), 2.2nF, ±5%, 50V, NP0, ±5%, SMD 0805; Manufacturer: YAGEO; Manufacturer Part Number: CC0805JKNPO9BN222
footprint CAP-0805 (0805 (2012M) Capacitor)
pins: 1, 2

## CC0805JKNPO9BN272
designator C?  Capacitance: 2.7nF  (hidden comment: *)
Capacitor, Ceramic (MLCC), 2.7nF, ±5%, 50V, NP0, ±5%, SMD 0805; Manufacturer: YAGEO; Manufacturer Part Number: CC0805JKNPO9BN272
footprint CAP-0805 (0805 (2012M) Capacitor)
pins: 1, 2

## CC0805JKNPO9BN332
designator C?  Capacitance: 3.3nF  (hidden comment: *)
Capacitor, Ceramic (MLCC), 3.3nF, ±5%, 50V, NP0, ±5%, SMD 0805; Manufacturer: YAGEO; Manufacturer Part Number: CC0805JKNPO9BN332
footprint CAP-0805 (0805 (2012M) Capacitor)
pins: 1, 2

## CC0805JKNPO9BN392
designator C?  Capacitance: 3.9nF  (hidden comment: *)
Capacitor, Ceramic (MLCC), 3.9nF, ±5%, 50V, NP0, ±5%, SMD 0805; Manufacturer: YAGEO; Manufacturer Part Number: CC0805JKNPO9BN392
footprint CAP-0805 (0805 (2012M) Capacitor)
pins: 1, 2

## CC0805JKNPO9BN472
designator C?  Capacitance: 4.7nF  (hidden comment: *)
Capacitor, Ceramic (MLCC), 4.7nF, ±5%, 50V, NP0, ±5%, SMD 0805; Manufacturer: YAGEO; Manufacturer Part Number: CC0805JKNPO9BN472
footprint CAP-0805 (0805 (2012M) Capacitor)
pins: 1, 2

## CC0805JKNPO9BN682
designator C?  Capacitance: 6.8nF  (hidden comment: *)
Capacitor, Ceramic (MLCC), 6.8nF, ±5%, 50V, NP0, ±5%, SMD 0805; Manufacturer: YAGEO; Manufacturer Part Number: CC0805JKNPO9BN682
footprint CAP-0805 (0805 (2012M) Capacitor)
pins: 1, 2

## CC0805JKNPOBBN102
designator C?  Capacitance: 1nF  (hidden comment: *)
Capacitor, Ceramic (MLCC), 1nF, ±5%, 500V, NP0, ±5%, SMD 0805; Manufacturer: YAGEO; Manufacturer Part Number: CC0805JKNPOBBN102
footprint CAP-0805 (0805 (2012M) Capacitor)
pins: 1, 2

## CC0805JKX7R7BB105
designator C?  Capacitance: 1uF  (hidden comment: *)
Capacitor, Ceramic (MLCC), 1uF, ±5%, 16V, X7R, ±5%, SMD 0805; Manufacturer: YAGEO; Manufacturer Part Number: CC0805JKX7R7BB105
footprint CAP-0805 (0805 (2012M) Capacitor)
pins: 1, 2

## CC0805JKX7R7BB334
designator C?  Capacitance: 330nF  (hidden comment: *)
Capacitor, Ceramic (MLCC), 330nF, ±5%, 16V, X7R, ±5%, SMD 0805; Manufacturer: YAGEO; Manufacturer Part Number: CC0805JKX7R7BB334
footprint CAP-0805 (0805 (2012M) Capacitor)
pins: 1, 2

## CC0805JKX7R7BB474
designator C?  Capacitance: 470nF  (hidden comment: *)
Capacitor, Ceramic (MLCC), 470nF, ±5%, 16V, X7R, ±5%, SMD 0805; Manufacturer: YAGEO; Manufacturer Part Number: CC0805JKX7R7BB474
footprint CAP-0805 (0805 (2012M) Capacitor)
pins: 1, 2

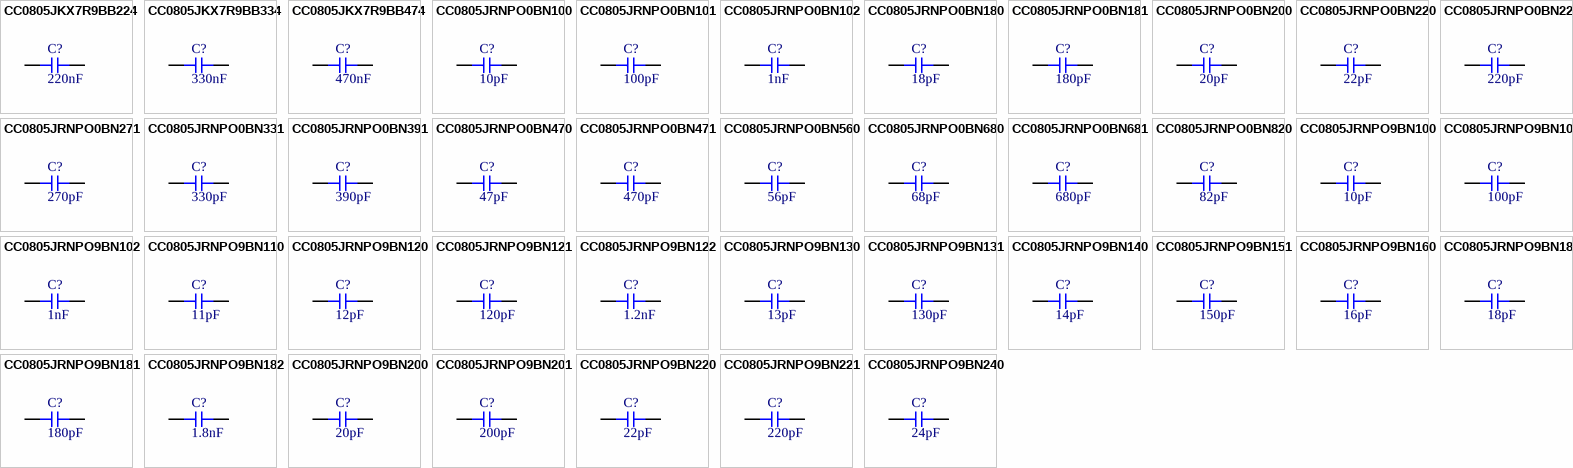
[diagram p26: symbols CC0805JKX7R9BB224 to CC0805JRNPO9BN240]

## CC0805JKX7R9BB224
designator C?  Capacitance: 220nF  (hidden comment: *)
Capacitor, Ceramic (MLCC), 220nF, ±5%, 50V, X7R, ±5%, SMD 0805; Manufacturer: YAGEO; Manufacturer Part Number: CC0805JKX7R9BB224
footprint CAP-0805 (0805 (2012M) Capacitor)
pins: 1, 2

## CC0805JKX7R9BB334
designator C?  Capacitance: 330nF  (hidden comment: *)
Capacitor, Ceramic (MLCC), 330nF, ±5%, 50V, X7R, ±5%, SMD 0805; Manufacturer: YAGEO; Manufacturer Part Number: CC0805JKX7R9BB334
footprint CAP-0805 (0805 (2012M) Capacitor)
pins: 1, 2

## CC0805JKX7R9BB474
designator C?  Capacitance: 470nF  (hidden comment: *)
Capacitor, Ceramic (MLCC), 470nF, ±5%, 50V, X7R, ±5%, SMD 0805; Manufacturer: YAGEO; Manufacturer Part Number: CC0805JKX7R9BB474
footprint CAP-0805 (0805 (2012M) Capacitor)
pins: 1, 2

## CC0805JRNPO0BN100
designator C?  Capacitance: 10pF  (hidden comment: *)
Capacitor, Ceramic (MLCC), 10pF, ±5%, 100V, NP0, ±5%, SMD 0805; Manufacturer: YAGEO; Manufacturer Part Number: CC0805JRNPO0BN100
footprint CAP-0805 (0805 (2012M) Capacitor)
pins: 1, 2

## CC0805JRNPO0BN101
designator C?  Capacitance: 100pF  (hidden comment: *)
Capacitor, Ceramic (MLCC), 100pF, ±5%, 100V, NP0, ±5%, SMD 0805; Manufacturer: YAGEO; Manufacturer Part Number: CC0805JRNPO0BN101
footprint CAP-0805 (0805 (2012M) Capacitor)
pins: 1, 2

## CC0805JRNPO0BN102
designator C?  Capacitance: 1nF  (hidden comment: *)
Capacitor, Ceramic (MLCC), 1nF, ±5%, 100V, NP0, ±5%, SMD 0805; Manufacturer: YAGEO; Manufacturer Part Number: CC0805JRNPO0BN102
footprint CAP-0805 (0805 (2012M) Capacitor)
pins: 1, 2

## CC0805JRNPO0BN180
designator C?  Capacitance: 18pF  (hidden comment: *)
Capacitor, Ceramic (MLCC), 18pF, ±5%, 100V, NP0, ±5%, SMD 0805; Manufacturer: YAGEO; Manufacturer Part Number: CC0805JRNPO0BN180
footprint CAP-0805 (0805 (2012M) Capacitor)
pins: 1, 2

## CC0805JRNPO0BN181
designator C?  Capacitance: 180pF  (hidden comment: *)
Capacitor, Ceramic (MLCC), 180pF, ±5%, 100V, NP0, ±5%, SMD 0805; Manufacturer: YAGEO; Manufacturer Part Number: CC0805JRNPO0BN181
footprint CAP-0805 (0805 (2012M) Capacitor)
pins: 1, 2

## CC0805JRNPO0BN200
designator C?  Capacitance: 20pF  (hidden comment: *)
Capacitor, Ceramic (MLCC), 20pF, ±5%, 100V, NP0, ±5%, SMD 0805; Manufacturer: YAGEO; Manufacturer Part Number: CC0805JRNPO0BN200
footprint CAP-0805 (0805 (2012M) Capacitor)
pins: 1, 2

## CC0805JRNPO0BN220
designator C?  Capacitance: 22pF  (hidden comment: *)
Capacitor, Ceramic (MLCC), 22pF, ±5%, 100V, NP0, ±5%, SMD 0805; Manufacturer: YAGEO; Manufacturer Part Number: CC0805JRNPO0BN220
footprint CAP-0805 (0805 (2012M) Capacitor)
pins: 1, 2

## CC0805JRNPO0BN221
designator C?  Capacitance: 220pF  (hidden comment: *)
Capacitor, Ceramic (MLCC), 220pF, ±5%, 100V, NP0, ±5%, SMD 0805; Manufacturer: YAGEO; Manufacturer Part Number: CC0805JRNPO0BN221
footprint CAP-0805 (0805 (2012M) Capacitor)
pins: 1, 2

## CC0805JRNPO0BN271
designator C?  Capacitance: 270pF  (hidden comment: *)
Capacitor, Ceramic (MLCC), 270pF, ±5%, 100V, NP0, ±5%, SMD 0805; Manufacturer: YAGEO; Manufacturer Part Number: CC0805JRNPO0BN271
footprint CAP-0805 (0805 (2012M) Capacitor)
pins: 1, 2

## CC0805JRNPO0BN331
designator C?  Capacitance: 330pF  (hidden comment: *)
Capacitor, Ceramic (MLCC), 330pF, ±5%, 100V, NP0, ±5%, SMD 0805; Manufacturer: YAGEO; Manufacturer Part Number: CC0805JRNPO0BN331
footprint CAP-0805 (0805 (2012M) Capacitor)
pins: 1, 2

## CC0805JRNPO0BN391
designator C?  Capacitance: 390pF  (hidden comment: *)
Capacitor, Ceramic (MLCC), 390pF, ±5%, 100V, NP0, ±5%, SMD 0805; Manufacturer: YAGEO; Manufacturer Part Number: CC0805JRNPO0BN391
footprint CAP-0805 (0805 (2012M) Capacitor)
pins: 1, 2

## CC0805JRNPO0BN470
designator C?  Capacitance: 47pF  (hidden comment: *)
Capacitor, Ceramic (MLCC), 47pF, ±5%, 100V, NP0, ±5%, SMD 0805; Manufacturer: YAGEO; Manufacturer Part Number: CC0805JRNPO0BN470
footprint CAP-0805 (0805 (2012M) Capacitor)
pins: 1, 2

## CC0805JRNPO0BN471
designator C?  Capacitance: 470pF  (hidden comment: *)
Capacitor, Ceramic (MLCC), 470pF, ±5%, 100V, NP0, ±5%, SMD 0805; Manufacturer: YAGEO; Manufacturer Part Number: CC0805JRNPO0BN471
footprint CAP-0805 (0805 (2012M) Capacitor)
pins: 1, 2

## CC0805JRNPO0BN560
designator C?  Capacitance: 56pF  (hidden comment: *)
Capacitor, Ceramic (MLCC), 56pF, ±5%, 100V, NP0, ±5%, SMD 0805; Manufacturer: YAGEO; Manufacturer Part Number: CC0805JRNPO0BN560
footprint CAP-0805 (0805 (2012M) Capacitor)
pins: 1, 2

## CC0805JRNPO0BN680
designator C?  Capacitance: 68pF  (hidden comment: *)
Capacitor, Ceramic (MLCC), 68pF, ±5%, 100V, NP0, ±5%, SMD 0805; Manufacturer: YAGEO; Manufacturer Part Number: CC0805JRNPO0BN680
footprint CAP-0805 (0805 (2012M) Capacitor)
pins: 1, 2

## CC0805JRNPO0BN681
designator C?  Capacitance: 680pF  (hidden comment: *)
Capacitor, Ceramic (MLCC), 680pF, ±5%, 100V, NP0, ±5%, SMD 0805; Manufacturer: YAGEO; Manufacturer Part Number: CC0805JRNPO0BN681
footprint CAP-0805 (0805 (2012M) Capacitor)
pins: 1, 2

## CC0805JRNPO0BN820
designator C?  Capacitance: 82pF  (hidden comment: *)
Capacitor, Ceramic (MLCC), 82pF, ±5%, 100V, NP0, ±5%, SMD 0805; Manufacturer: YAGEO; Manufacturer Part Number: CC0805JRNPO0BN820
footprint CAP-0805 (0805 (2012M) Capacitor)
pins: 1, 2

## CC0805JRNPO9BN100
designator C?  Capacitance: 10pF  (hidden comment: *)
Capacitor, Ceramic (MLCC), 10pF, ±5%, 50V, NP0, ±5%, SMD 0805; Manufacturer: YAGEO; Manufacturer Part Number: CC0805JRNPO9BN100
footprint CAP-0805 (0805 (2012M) Capacitor)
pins: 1, 2

## CC0805JRNPO9BN101
designator C?  Capacitance: 100pF  (hidden comment: *)
Capacitor, Ceramic (MLCC), 100pF, ±5%, 50V, NP0, ±5%, SMD 0805; Manufacturer: YAGEO; Manufacturer Part Number: CC0805JRNPO9BN101
footprint CAP-0805 (0805 (2012M) Capacitor)
pins: 1, 2

## CC0805JRNPO9BN102
designator C?  Capacitance: 1nF  (hidden comment: *)
Capacitor, Ceramic (MLCC), 1nF, ±5%, 50V, NP0, ±5%, SMD 0805; Manufacturer: YAGEO; Manufacturer Part Number: CC0805JRNPO9BN102
footprint CAP-0805 (0805 (2012M) Capacitor)
pins: 1, 2

## CC0805JRNPO9BN110
designator C?  Capacitance: 11pF  (hidden comment: *)
Capacitor, Ceramic (MLCC), 11pF, ±5%, 50V, NP0, ±5%, SMD 0805; Manufacturer: YAGEO; Manufacturer Part Number: CC0805JRNPO9BN110
footprint CAP-0805 (0805 (2012M) Capacitor)
pins: 1, 2

## CC0805JRNPO9BN120
designator C?  Capacitance: 12pF  (hidden comment: *)
Capacitor, Ceramic (MLCC), 12pF, ±5%, 50V, NP0, ±5%, SMD 0805; Manufacturer: YAGEO; Manufacturer Part Number: CC0805JRNPO9BN120
footprint CAP-0805 (0805 (2012M) Capacitor)
pins: 1, 2

## CC0805JRNPO9BN121
designator C?  Capacitance: 120pF  (hidden comment: *)
Capacitor, Ceramic (MLCC), 120pF, ±5%, 50V, NP0, ±5%, SMD 0805; Manufacturer: YAGEO; Manufacturer Part Number: CC0805JRNPO9BN121
footprint CAP-0805 (0805 (2012M) Capacitor)
pins: 1, 2

## CC0805JRNPO9BN122
designator C?  Capacitance: 1.2nF  (hidden comment: *)
Capacitor, Ceramic (MLCC), 1.2nF, ±5%, 50V, NP0, ±5%, SMD 0805; Manufacturer: YAGEO; Manufacturer Part Number: CC0805JRNPO9BN122
footprint CAP-0805 (0805 (2012M) Capacitor)
pins: 1, 2

## CC0805JRNPO9BN130
designator C?  Capacitance: 13pF  (hidden comment: *)
Capacitor, Ceramic (MLCC), 13pF, ±5%, 50V, NP0, ±5%, SMD 0805; Manufacturer: YAGEO; Manufacturer Part Number: CC0805JRNPO9BN130
footprint CAP-0805 (0805 (2012M) Capacitor)
pins: 1, 2

## CC0805JRNPO9BN131
designator C?  Capacitance: 130pF  (hidden comment: *)
Capacitor, Ceramic (MLCC), 130pF, ±5%, 50V, NP0, ±5%, SMD 0805; Manufacturer: YAGEO; Manufacturer Part Number: CC0805JRNPO9BN131
footprint CAP-0805 (0805 (2012M) Capacitor)
pins: 1, 2

## CC0805JRNPO9BN140
designator C?  Capacitance: 14pF  (hidden comment: *)
Capacitor, Ceramic (MLCC), 14pF, ±5%, 50V, NP0, ±5%, SMD 0805; Manufacturer: YAGEO; Manufacturer Part Number: CC0805JRNPO9BN140
footprint CAP-0805 (0805 (2012M) Capacitor)
pins: 1, 2

## CC0805JRNPO9BN151
designator C?  Capacitance: 150pF  (hidden comment: *)
Capacitor, Ceramic (MLCC), 150pF, ±5%, 50V, NP0, ±5%, SMD 0805; Manufacturer: YAGEO; Manufacturer Part Number: CC0805JRNPO9BN151
footprint CAP-0805 (0805 (2012M) Capacitor)
pins: 1, 2

## CC0805JRNPO9BN160
designator C?  Capacitance: 16pF  (hidden comment: *)
Capacitor, Ceramic (MLCC), 16pF, ±5%, 50V, NP0, ±5%, SMD 0805; Manufacturer: YAGEO; Manufacturer Part Number: CC0805JRNPO9BN160
footprint CAP-0805 (0805 (2012M) Capacitor)
pins: 1, 2

## CC0805JRNPO9BN180
designator C?  Capacitance: 18pF  (hidden comment: *)
Capacitor, Ceramic (MLCC), 18pF, ±5%, 50V, NP0, ±5%, SMD 0805; Manufacturer: YAGEO; Manufacturer Part Number: CC0805JRNPO9BN180
footprint CAP-0805 (0805 (2012M) Capacitor)
pins: 1, 2

## CC0805JRNPO9BN181
designator C?  Capacitance: 180pF  (hidden comment: *)
Capacitor, Ceramic (MLCC), 180pF, ±5%, 50V, NP0, ±5%, SMD 0805; Manufacturer: YAGEO; Manufacturer Part Number: CC0805JRNPO9BN181
footprint CAP-0805 (0805 (2012M) Capacitor)
pins: 1, 2

## CC0805JRNPO9BN182
designator C?  Capacitance: 1.8nF  (hidden comment: *)
Capacitor, Ceramic (MLCC), 1.8nF, ±5%, 50V, NP0, ±5%, SMD 0805; Manufacturer: YAGEO; Manufacturer Part Number: CC0805JRNPO9BN182
footprint CAP-0805 (0805 (2012M) Capacitor)
pins: 1, 2

## CC0805JRNPO9BN200
designator C?  Capacitance: 20pF  (hidden comment: *)
Capacitor, Ceramic (MLCC), 20pF, ±5%, 50V, NP0, ±5%, SMD 0805; Manufacturer: YAGEO; Manufacturer Part Number: CC0805JRNPO9BN200
footprint CAP-0805 (0805 (2012M) Capacitor)
pins: 1, 2

## CC0805JRNPO9BN201
designator C?  Capacitance: 200pF  (hidden comment: *)
Capacitor, Ceramic (MLCC), 200pF, ±5%, 50V, NP0, ±5%, SMD 0805; Manufacturer: YAGEO; Manufacturer Part Number: CC0805JRNPO9BN201
footprint CAP-0805 (0805 (2012M) Capacitor)
pins: 1, 2

## CC0805JRNPO9BN220
designator C?  Capacitance: 22pF  (hidden comment: *)
Capacitor, Ceramic (MLCC), 22pF, ±5%, 50V, NP0, ±5%, SMD 0805; Manufacturer: YAGEO; Manufacturer Part Number: CC0805JRNPO9BN220
footprint CAP-0805 (0805 (2012M) Capacitor)
pins: 1, 2

## CC0805JRNPO9BN221
designator C?  Capacitance: 220pF  (hidden comment: *)
Capacitor, Ceramic (MLCC), 220pF, ±5%, 50V, NP0, ±5%, SMD 0805; Manufacturer: YAGEO; Manufacturer Part Number: CC0805JRNPO9BN221
footprint CAP-0805 (0805 (2012M) Capacitor)
pins: 1, 2

## CC0805JRNPO9BN240
designator C?  Capacitance: 24pF  (hidden comment: *)
Capacitor, Ceramic (MLCC), 24pF, ±5%, 50V, NP0, ±5%, SMD 0805; Manufacturer: YAGEO; Manufacturer Part Number: CC0805JRNPO9BN240
footprint CAP-0805 (0805 (2012M) Capacitor)
pins: 1, 2

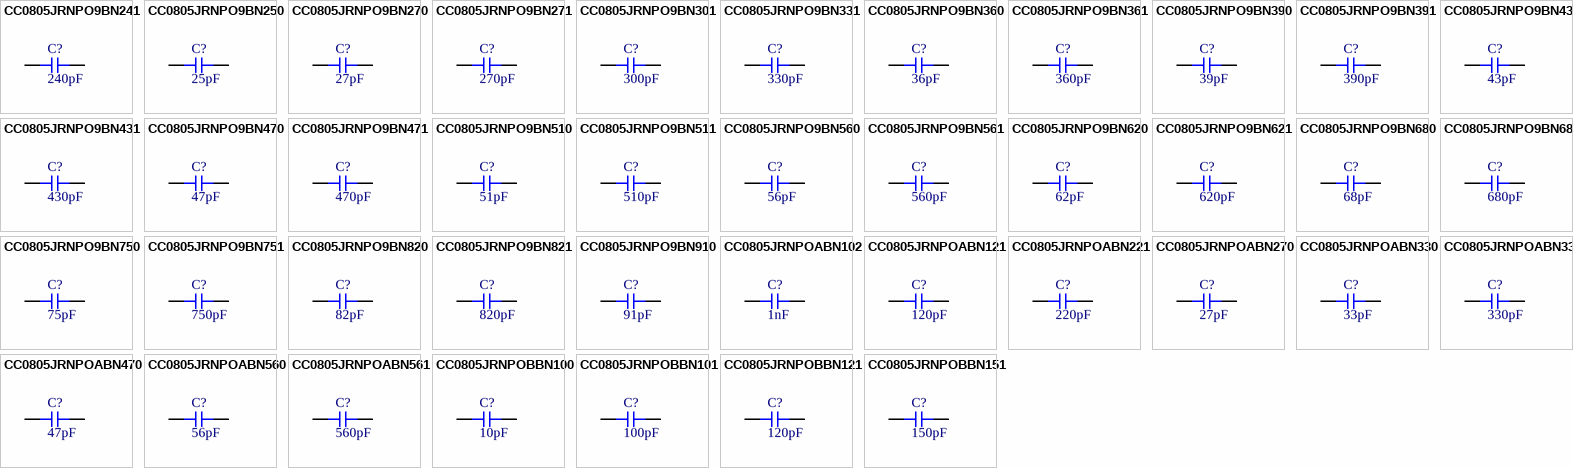
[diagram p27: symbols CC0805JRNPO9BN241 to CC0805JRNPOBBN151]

## CC0805JRNPO9BN241
designator C?  Capacitance: 240pF  (hidden comment: *)
Capacitor, Ceramic (MLCC), 240pF, ±5%, 50V, NP0, ±5%, SMD 0805; Manufacturer: YAGEO; Manufacturer Part Number: CC0805JRNPO9BN241
footprint CAP-0805 (0805 (2012M) Capacitor)
pins: 1, 2

## CC0805JRNPO9BN250
designator C?  Capacitance: 25pF  (hidden comment: *)
Capacitor, Ceramic (MLCC), 25pF, ±5%, 50V, NP0, ±5%, SMD 0805; Manufacturer: YAGEO; Manufacturer Part Number: CC0805JRNPO9BN250
footprint CAP-0805 (0805 (2012M) Capacitor)
pins: 1, 2

## CC0805JRNPO9BN270
designator C?  Capacitance: 27pF  (hidden comment: *)
Capacitor, Ceramic (MLCC), 27pF, ±5%, 50V, NP0, ±5%, SMD 0805; Manufacturer: YAGEO; Manufacturer Part Number: CC0805JRNPO9BN270
footprint CAP-0805 (0805 (2012M) Capacitor)
pins: 1, 2

## CC0805JRNPO9BN271
designator C?  Capacitance: 270pF  (hidden comment: *)
Capacitor, Ceramic (MLCC), 270pF, ±5%, 50V, NP0, ±5%, SMD 0805; Manufacturer: YAGEO; Manufacturer Part Number: CC0805JRNPO9BN271
footprint CAP-0805 (0805 (2012M) Capacitor)
pins: 1, 2

## CC0805JRNPO9BN301
designator C?  Capacitance: 300pF  (hidden comment: *)
Capacitor, Ceramic (MLCC), 300pF, ±5%, 50V, NP0, ±5%, SMD 0805; Manufacturer: YAGEO; Manufacturer Part Number: CC0805JRNPO9BN301
footprint CAP-0805 (0805 (2012M) Capacitor)
pins: 1, 2

## CC0805JRNPO9BN331
designator C?  Capacitance: 330pF  (hidden comment: *)
Capacitor, Ceramic (MLCC), 330pF, ±5%, 50V, NP0, ±5%, SMD 0805; Manufacturer: YAGEO; Manufacturer Part Number: CC0805JRNPO9BN331
footprint CAP-0805 (0805 (2012M) Capacitor)
pins: 1, 2

## CC0805JRNPO9BN360
designator C?  Capacitance: 36pF  (hidden comment: *)
Capacitor, Ceramic (MLCC), 36pF, ±5%, 50V, NP0, ±5%, SMD 0805; Manufacturer: YAGEO; Manufacturer Part Number: CC0805JRNPO9BN360
footprint CAP-0805 (0805 (2012M) Capacitor)
pins: 1, 2

## CC0805JRNPO9BN361
designator C?  Capacitance: 360pF  (hidden comment: *)
Capacitor, Ceramic (MLCC), 360pF, ±5%, 50V, NP0, ±5%, SMD 0805; Manufacturer: YAGEO; Manufacturer Part Number: CC0805JRNPO9BN361
footprint CAP-0805 (0805 (2012M) Capacitor)
pins: 1, 2

## CC0805JRNPO9BN390
designator C?  Capacitance: 39pF  (hidden comment: *)
Capacitor, Ceramic (MLCC), 39pF, ±5%, 50V, NP0, ±5%, SMD 0805; Manufacturer: YAGEO; Manufacturer Part Number: CC0805JRNPO9BN390
footprint CAP-0805 (0805 (2012M) Capacitor)
pins: 1, 2

## CC0805JRNPO9BN391
designator C?  Capacitance: 390pF  (hidden comment: *)
Capacitor, Ceramic (MLCC), 390pF, ±5%, 50V, NP0, ±5%, SMD 0805; Manufacturer: YAGEO; Manufacturer Part Number: CC0805JRNPO9BN391
footprint CAP-0805 (0805 (2012M) Capacitor)
pins: 1, 2

## CC0805JRNPO9BN430
designator C?  Capacitance: 43pF  (hidden comment: *)
Capacitor, Ceramic (MLCC), 43pF, ±5%, 50V, NP0, ±5%, SMD 0805; Manufacturer: YAGEO; Manufacturer Part Number: CC0805JRNPO9BN430
footprint CAP-0805 (0805 (2012M) Capacitor)
pins: 1, 2

## CC0805JRNPO9BN431
designator C?  Capacitance: 430pF  (hidden comment: *)
Capacitor, Ceramic (MLCC), 430pF, ±5%, 50V, NP0, ±5%, SMD 0805; Manufacturer: YAGEO; Manufacturer Part Number: CC0805JRNPO9BN431
footprint CAP-0805 (0805 (2012M) Capacitor)
pins: 1, 2

## CC0805JRNPO9BN470
designator C?  Capacitance: 47pF  (hidden comment: *)
Capacitor, Ceramic (MLCC), 47pF, ±5%, 50V, NP0, ±5%, SMD 0805; Manufacturer: YAGEO; Manufacturer Part Number: CC0805JRNPO9BN470
footprint CAP-0805 (0805 (2012M) Capacitor)
pins: 1, 2

## CC0805JRNPO9BN471
designator C?  Capacitance: 470pF  (hidden comment: *)
Capacitor, Ceramic (MLCC), 470pF, ±5%, 50V, NP0, ±5%, SMD 0805; Manufacturer: YAGEO; Manufacturer Part Number: CC0805JRNPO9BN471
footprint CAP-0805 (0805 (2012M) Capacitor)
pins: 1, 2

## CC0805JRNPO9BN510
designator C?  Capacitance: 51pF  (hidden comment: *)
Capacitor, Ceramic (MLCC), 51pF, ±5%, 50V, NP0, ±5%, SMD 0805; Manufacturer: YAGEO; Manufacturer Part Number: CC0805JRNPO9BN510
footprint CAP-0805 (0805 (2012M) Capacitor)
pins: 1, 2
